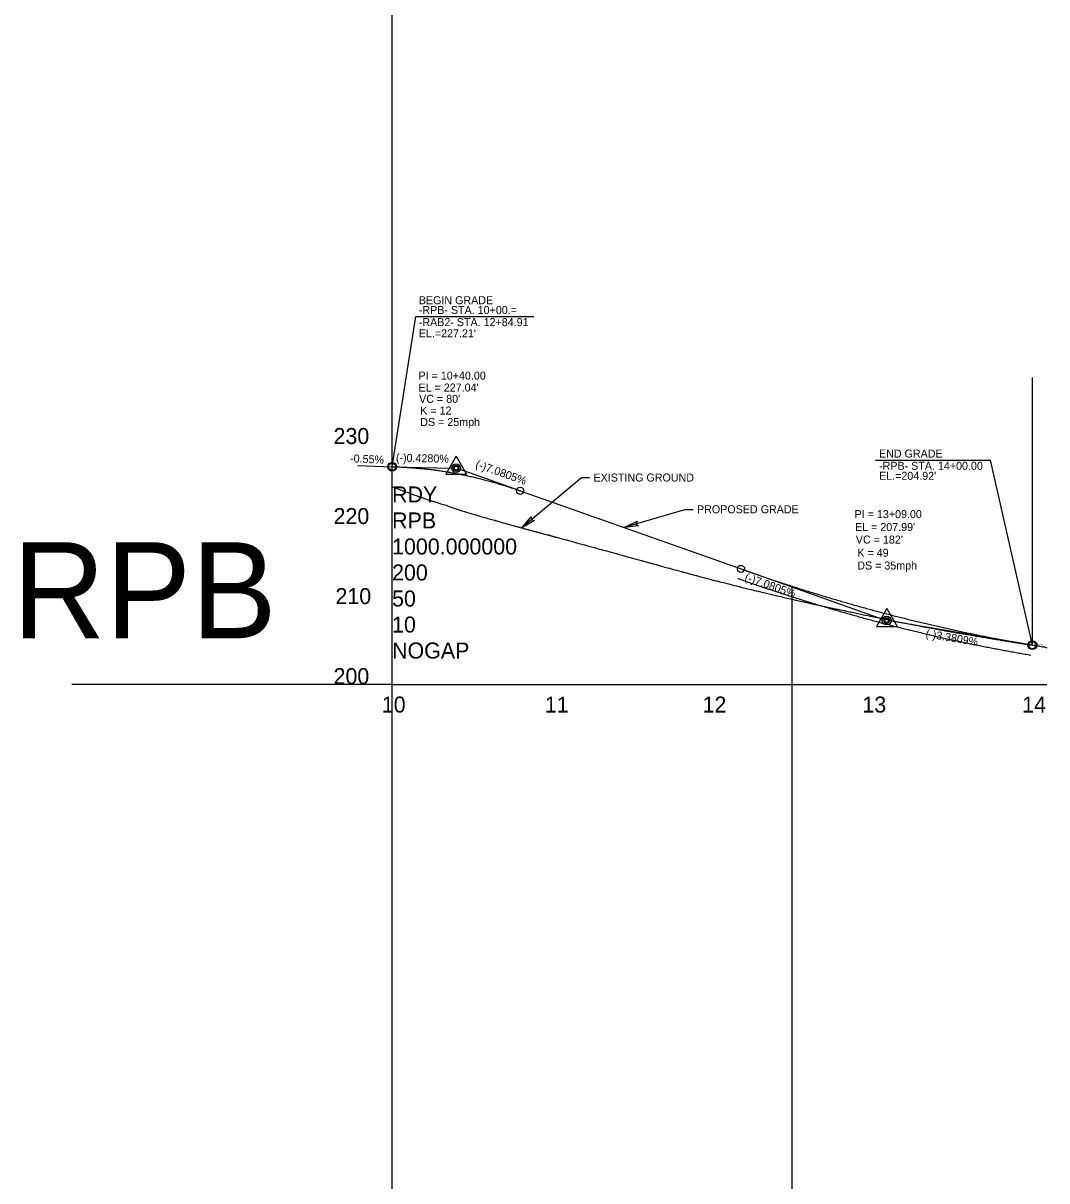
# Model space of a CAD drawing. Extents: x 2115752 to 2121174, y 562881 to 567245.
# Drawn here: x 2116466 to 2117105, y 564327 to 565050 of the extents above; entities that cross this region are included whole.
import ezdxf

# ---------------------------------------------------------------- set-up
doc = ezdxf.new("R2010")
doc.units = 0
for name, color, linetype in [('Exist Profile Cell', 7, 'Continuous'), ('Exist Vertical Profile Ground Line', 7, 'Continuous'), ('Exist Vertical Profile Horizontal Axis Label Major', 7, 'Continuous'), ('Exist Vertical Profile Vertical Axis Label', 7, 'Continuous'), ('Prop PFL VPI Symbol CELL', 7, 'Continuous'), ('Prop Terminator CELL', 7, 'Continuous'), ('Prop Vertical Profile Curve Label', 7, 'Continuous'), ('Prop Vertical Profile Grade', 7, 'Continuous'), ('Prop Vertical Profile Grade Label', 7, 'Continuous'), ('Prop VPI Label', 7, 'Continuous'), ('Scratch_Level_1', 7, 'Continuous')]:
    doc.layers.add(name, color=color, linetype=linetype)

msp = doc.modelspace()

# ---------------------------------------------------------------- linework, layer by layer
at = {"layer": 'Exist Profile Cell'}
for q in [(2116696.3, 564887.02), (2117105.35, 564637.02), (2116696.3, 564637.02)]:
    msp.add_line((2116696.3, 564637.02), q, dxfattribs=at)
at = {"layer": 'Exist Vertical Profile Ground Line'}
for points in [[(2116696.3, 564760.59), (2116696.8, 564760.39), (2116697.3, 564760.25), (2116699.53, 564759.41), (2116701.4, 564758.73), (2116702.12, 564758.46), (2116702.66, 564758.26), (2116703.96, 564757.68), (2116705.79, 564757.11), (2116707.51, 564756.4), (2116708.91, 564755.92), (2116709.33, 564755.73), (2116709.91, 564755.57), (2116712.03, 564754.81), (2116712.91, 564754.45), (2116714.1, 564754.12), (2116715.14, 564753.76), (2116716.48, 564753.23), (2116718.31, 564752.67), (2116720.06, 564752.04), (2116721.37, 564751.63), (2116721.85, 564751.46), (2116722.49, 564751.28), (2116724.45, 564750.65), (2116726.71, 564749.99), (2116727.54, 564749.74), (2116730.01, 564748.97), (2116730.88, 564748.68), (2116732.55, 564748.07), (2116733.77, 564747.65), (2116734.34, 564747.41), (2116735.1, 564747.16), (2116736.87, 564746.54), (2116739.32, 564745.73), (2116739.96, 564745.53), (2116741.47, 564745.04), (2116743.44, 564744.48), (2116745.04, 564743.98), (2116746.2, 564743.65), (2116747.7, 564743.21), (2116748.63, 564742.95), (2116749.31, 564742.75), (2116750.43, 564742.42), (2116752.42, 564741.87), (2116754.03, 564741.4), (2116755.82, 564740.9), (2116756.21, 564740.79), (2116757.61, 564740.41), (2116758.65, 564740.11), (2116760.4, 564739.6), (2116761.17, 564739.38), (2116761.76, 564739.2), (2116762.97, 564738.85), (2116764.87, 564738.32), (2116766.53, 564737.83), (2116768, 564737.44), (2116768.34, 564737.35), (2116768.8, 564737.22), (2116771.09, 564736.55), (2116771.87, 564736.33), (2116772.96, 564736.03), (2116774.2, 564735.68), (2116777.29, 564734.84), (2116779.02, 564734.38), (2116780.4, 564734), (2116781.24, 564733.77), (2116782.56, 564733.41), (2116783.52, 564733.15), (2116784.39, 564732.93), (2116785.56, 564732.62), (2116786.63, 564732.34), (2116789.74, 564731.54), (2116791.57, 564731.06), (2116792.87, 564730.72), (2116793.92, 564730.44), (2116795.94, 564729.9), (2116798.1, 564729.31), (2116798.66, 564729.16), (2116799.07, 564729.05), (2116800.5, 564728.65), (2116802.37, 564728.14), (2116805.3, 564727.35), (2116806.51, 564727), (2116808.36, 564726.49), (2116809.36, 564726.21), (2116810.71, 564725.84), (2116811.15, 564725.72), (2116811.47, 564725.63), (2116812.94, 564725.22), (2116814.92, 564724.68), (2116816.55, 564724.2), (2116817.75, 564723.87), (2116818.35, 564723.7), (2116819.15, 564723.48), (2116820.87, 564723), (2116823.34, 564722.34), (2116823.98, 564722.17), (2116825.77, 564721.69), (2116827.08, 564721.32), (2116827.54, 564721.2), (2116830.16, 564720.48)], [(2116830.16, 564720.48), (2116831.77, 564720.05), (2116833.25, 564719.64), (2116836.36, 564718.8), (2116837.99, 564718.33), (2116839.79, 564717.86), (2116840.11, 564717.77), (2116842.64, 564717.08), (2116843.35, 564716.88), (2116844.3, 564716.63), (2116845.73, 564716.24), (2116848.8, 564715.4), (2116850.51, 564714.92), (2116851.98, 564714.52), (2116852.29, 564714.43), (2116852.68, 564714.33), (2116855.06, 564713.66), (2116857.02, 564713.12), (2116857.66, 564712.94), (2116858.15, 564712.8), (2116859.44, 564712.43), (2116861.32, 564711.92), (2116861.86, 564711.77), (2116864.36, 564711.07), (2116865.43, 564710.78), (2116866.59, 564710.44), (2116867.49, 564710.22), (2116868.39, 564709.98), (2116869.58, 564709.66), (2116870.18, 564709.49), (2116870.63, 564709.37), (2116871.96, 564708.99), (2116874.02, 564708.44), (2116876.85, 564707.66), (2116877.31, 564707.53), (2116877.92, 564707.37), (2116879.94, 564706.81), (2116882.23, 564706.2), (2116882.69, 564706.07), (2116883.04, 564705.97), (2116885.19, 564705.41), (2116886.14, 564705.15), (2116886.5, 564705.05), (2116888.06, 564704.61), (2116889.28, 564704.31), (2116889.88, 564704.16), (2116890.7, 564703.94), (2116891.65, 564703.67), (2116892.38, 564703.49), (2116893.44, 564703.21), (2116894.92, 564702.84), (2116895.5, 564702.69), (2116897.01, 564702.27), (2116898.61, 564701.88), (2116899.13, 564701.75), (2116901.71, 564701.07), (2116903.28, 564700.67), (2116904.82, 564700.27), (2116907.34, 564699.63), (2116907.94, 564699.48), (2116909.98, 564698.96), (2116911.4, 564698.6), (2116913.01, 564698.17), (2116914.16, 564697.9), (2116914.83, 564697.73), (2116915.77, 564697.5), (2116916.66, 564697.28), (2116917.28, 564697.12), (2116918.48, 564696.81), (2116920.4, 564696.36), (2116921.17, 564696.17), (2116923.48, 564695.61), (2116924.09, 564695.46), (2116926.61, 564694.85), (2116927.33, 564694.68), (2116928.37, 564694.43), (2116929.17, 564694.24), (2116929.72, 564694.11), (2116931.01, 564693.8), (2116932.85, 564693.38), (2116933.39, 564693.26), (2116935.93, 564692.66), (2116936.23, 564692.59), (2116936.66, 564692.49), (2116938.08, 564692.16), (2116939.05, 564691.94), (2116939.92, 564691.73), (2116941.12, 564691.47), (2116942.17, 564691.23), (2116945.27, 564690.53), (2116947.04, 564690.12), (2116948.4, 564689.82), (2116948.9, 564689.7), (2116949.51, 564689.57), (2116951.48, 564689.13), (2116952.32, 564688.93), (2116953.56, 564688.66), (2116954.18, 564688.52), (2116954.61, 564688.43), (2116957.74, 564687.72), (2116959.48, 564687.31)], [(2116959.48, 564687.31), (2116960.82, 564687.01), (2116961.35, 564686.89), (2116962.11, 564686.73), (2116963.93, 564686.33), (2116966.09, 564685.86), (2116966.65, 564685.75), (2116967.04, 564685.66), (2116968.52, 564685.32), (2116970.49, 564684.92), (2116973.24, 564684.33), (2116973.83, 564684.19), (2116974.69, 564684.02), (2116976.35, 564683.66), (2116978.7, 564683.17), (2116979.16, 564683.08), (2116979.49, 564683.01), (2116981.04, 564682.67), (2116982.59, 564682.37), (2116983, 564682.29), (2116984.49, 564681.97), (2116985.69, 564681.72), (2116986.38, 564681.57), (2116987.34, 564681.38), (2116988.86, 564681.07), (2116991.92, 564680.43), (2116993.42, 564680.13), (2116995.01, 564679.8), (2116995.5, 564679.7), (2116997.1, 564679.38), (2116998.16, 564679.17), (2116999.78, 564678.84), (2117000.57, 564678.68), (2117001.21, 564678.55), (2117002.46, 564678.28), (2117004.42, 564677.9), (2117005.18, 564677.75), (2117007.46, 564677.27), (2117007.84, 564677.19), (2117008.36, 564677.09), (2117010.62, 564676.65), (2117012.5, 564676.29), (2117013.69, 564676.05), (2117016.8, 564675.44), (2117017.35, 564675.33), (2117019.91, 564674.82), (2117020.75, 564674.65), (2117022.98, 564674.2), (2117024.95, 564673.82), (2117025.65, 564673.69), (2117026.15, 564673.59), (2117027.5, 564673.29), (2117029.4, 564672.96), (2117032.3, 564672.4), (2117033.34, 564672.2), (2117034.58, 564671.95), (2117035.5, 564671.79), (2117036.46, 564671.6), (2117037.6, 564671.41), (2117038.54, 564671.24), (2117041.18, 564670.77), (2117041.77, 564670.67), (2117043.53, 564670.34), (2117044.84, 564670.12), (2117045.39, 564670.02), (2117046.05, 564669.92), (2117047.91, 564669.6), (2117048.96, 564669.41), (2117050.21, 564669.21), (2117050.62, 564669.14), (2117050.96, 564669.08), (2117053.13, 564668.72), (2117054.39, 564668.51), (2117057.22, 564668.02), (2117057.83, 564667.91), (2117058.59, 564667.79), (2117059.59, 564667.62), (2117060.34, 564667.49), (2117061.44, 564667.29), (2117062.78, 564667.08), (2117063.42, 564666.97), (2117065.02, 564666.68), (2117066.98, 564666.36), (2117068.59, 564666.07), (2117069.64, 564665.9), (2117070.31, 564665.78), (2117071.23, 564665.64), (2117072.15, 564665.48), (2117072.77, 564665.37), (2117073.91, 564665.17), (2117075.9, 564664.85), (2117077.51, 564664.57), (2117079.02, 564664.34), (2117079.74, 564664.23), (2117081.1, 564663.99), (2117082.17, 564663.82), (2117083.92, 564663.54), (2117084.67, 564663.42), (2117085.28, 564663.32), (2117088.34, 564662.83), (2117089.04, 564662.73)], [(2117089.04, 564662.73), (2117091.39, 564662.36), (2117091.76, 564662.31), (2117092.22, 564662.24), (2117094.52, 564661.88), (2117095.34, 564661.75), (2117096.44, 564661.59), (2117097.16, 564661.48), (2117097.66, 564661.4), (2117098.94, 564661.2), (2117100.78, 564660.96), (2117102.54, 564660.68), (2117103.95, 564660.48), (2117104.36, 564660.42), (2117105.35, 564659.88)]]:
    msp.add_lwpolyline(points, dxfattribs=at)
at = {"layer": 'Prop PFL VPI Symbol CELL'}
for p, q in [((2116736.3, 564779.71), (2116729.85, 564768.51)), ((2116736.3, 564779.71), (2116742.8, 564768.51)), ((2116729.85, 564768.51), (2116742.8, 564768.51)), ((2117005.3, 564684.47), (2116998.85, 564673.27)), ((2117005.3, 564684.47), (2117011.8, 564673.27)), ((2116998.85, 564673.27), (2117011.8, 564673.27))]:
    msp.add_line(p, q, dxfattribs=at)
for centre, radius in [((2116736.3, 564772.22), 1.75), ((2116736.3, 564772.22), 1.2), ((2117005.3, 564676.99), 1.75), ((2117005.3, 564676.99), 1.2)]:
    msp.add_circle(centre, radius, dxfattribs=at)
at = {"layer": 'Prop Terminator CELL'}
for points in [[(2116785.19, 564739.42), (2116777.29, 564734.84), (2116783.21, 564741.87), (2116783.35, 564739.9)], [(2116850.35, 564736.1), (2116841.27, 564735.06), (2116849.51, 564739.14), (2116848.85, 564737.28)]]:
    msp.add_lwpolyline(points, close=True, dxfattribs=at)
at = {"layer": 'Prop Vertical Profile Curve Label'}
for centre in [(2116696.3, 564773.08), (2116776.3, 564758.06), (2116914.3, 564709.21), (2117096.3, 564661.61)]:
    msp.add_circle(centre, 2.25, dxfattribs=at)
at = {"layer": 'Prop Vertical Profile Grade'}
for p, q in [((2116776.3, 564758.06), (2116914.3, 564709.21)), ((2117095.3, 564661.78), (2117096.3, 564661.61))]:
    msp.add_line(p, q, dxfattribs=at)
for points in [[(2116696.3, 564773.08), (2116697.9, 564773.04), (2116699.5, 564772.99), (2116701.1, 564772.93), (2116702.7, 564772.86), (2116704.3, 564772.78), (2116705.9, 564772.68), (2116707.5, 564772.58), (2116709.1, 564772.47), (2116710.7, 564772.34), (2116712.3, 564772.21), (2116713.9, 564772.06), (2116715.5, 564771.9), (2116717.1, 564771.74), (2116718.7, 564771.56), (2116720.3, 564771.37), (2116721.9, 564771.17), (2116723.5, 564770.96), (2116725.1, 564770.74), (2116726.7, 564770.51), (2116728.3, 564770.27), (2116729.9, 564770.01), (2116731.5, 564769.75), (2116733.1, 564769.48), (2116734.7, 564769.19), (2116736.3, 564768.9), (2116737.9, 564768.59), (2116739.5, 564768.28), (2116741.1, 564767.95), (2116742.7, 564767.61), (2116744.3, 564767.26), (2116745.9, 564766.9), (2116747.5, 564766.54), (2116749.1, 564766.15), (2116750.7, 564765.76), (2116752.3, 564765.36), (2116753.9, 564764.95), (2116755.5, 564764.53), (2116757.1, 564764.09), (2116758.7, 564763.65), (2116760.3, 564763.2), (2116761.9, 564762.73), (2116763.5, 564762.25), (2116765.1, 564761.77), (2116766.7, 564761.27), (2116768.3, 564760.76), (2116769.9, 564760.24), (2116771.5, 564759.71), (2116773.1, 564759.18), (2116774.7, 564758.62), (2116776.3, 564758.06)], [(2116914.3, 564709.21), (2116917.94, 564707.93), (2116921.58, 564706.66), (2116925.22, 564705.4), (2116928.86, 564704.16), (2116932.5, 564702.93), (2116936.14, 564701.72), (2116939.78, 564700.52), (2116943.42, 564699.33), (2116947.06, 564698.16), (2116950.7, 564696.99), (2116954.34, 564695.85), (2116957.98, 564694.71), (2116961.62, 564693.59), (2116965.26, 564692.49), (2116968.9, 564691.39), (2116972.54, 564690.31), (2116976.18, 564689.25), (2116979.82, 564688.19), (2116983.46, 564687.15), (2116987.1, 564686.13), (2116990.74, 564685.12), (2116994.38, 564684.12), (2116998.02, 564683.13), (2117001.66, 564682.16), (2117005.3, 564681.2), (2117008.94, 564680.25), (2117012.58, 564679.32), (2117016.22, 564678.4), (2117019.86, 564677.5), (2117023.5, 564676.61), (2117027.14, 564675.73), (2117030.78, 564674.87), (2117034.42, 564674.01), (2117038.06, 564673.18), (2117041.7, 564672.35), (2117045.34, 564671.54), (2117048.98, 564670.75), (2117052.62, 564669.96), (2117056.26, 564669.19), (2117059.9, 564668.43), (2117063.54, 564667.69), (2117067.18, 564666.96), (2117070.82, 564666.25), (2117074.46, 564665.54), (2117078.1, 564664.85), (2117081.74, 564664.18), (2117085.38, 564663.51), (2117089.02, 564662.87), (2117092.66, 564662.23), (2117096.3, 564661.61)]]:
    msp.add_spline(points, degree=3, dxfattribs=at)
at = {"layer": 'Prop VPI Label'}
for p, q in [((2116696.3, 564773.08), (2116711.22, 564866.89)), ((2116711.22, 564866.89), (2116784.91, 564866.89)), ((2116674.78, 564773.95), (2116696.3, 564773.08)), ((2116696.3, 564773.08), (2116733.55, 564772.28)), ((2116776.3, 564758.06), (2116738.9, 564771.31)), ((2116998.27, 564777.09), (2117070.2, 564777.09)), ((2117096.3, 564661.61), (2117070.2, 564777.09)), ((2116914.3, 564709.21), (2117002.71, 564677.91)), ((2117096.3, 564661.61), (2117008.02, 564676.53))]:
    msp.add_line(p, q, dxfattribs=at)
for points in [[(2116819.71, 564766.07), (2116814.74, 564766.07), (2116777.29, 564734.84)], [(2116884.38, 564746.12), (2116879.08, 564746.12), (2116841.27, 564735.06)]]:
    msp.add_lwpolyline(points, dxfattribs=at)
for centre in [(2116696.3, 564773.08), (2116736.3, 564772.22), (2117005.3, 564676.99), (2117096.3, 564661.61)]:
    msp.add_circle(centre, 2.75, dxfattribs=at)
at = {"layer": 'Scratch_Level_1'}
for p, q in [((2116696.3, 564637.02), (2116696.3, 565506.42)), ((2117096.3, 564661.61), (2117096.3, 564828.74)), ((2116718.31, 564752.67), (2116724.45, 564750.65)), ((2116768, 564737.44), (2116798.66, 564729.16)), ((2116946.3, 563767.63), (2116946.3, 564698.4)), ((2117046.3, 564669.87), (2117066.98, 564666.36)), ((2117076.3, 564664.78), (2117088.34, 564662.83)), ((2117096.3, 564661.61), (2117100.78, 564660.96)), ((2116696.3, 564637.02), (2116496.27, 564637.02)), ((2116696.3, 563767.63), (2116696.3, 564637.02))]:
    msp.add_line(p, q, dxfattribs=at)
msp.add_spline([(2116912.23, 564703.31), (2116915.88, 564702.03), (2116919.54, 564700.75), (2116923.2, 564699.49), (2116926.86, 564698.24), (2116930.52, 564697.01), (2116934.18, 564695.79), (2116937.84, 564694.58), (2116941.5, 564693.38), (2116945.16, 564692.2), (2116948.82, 564691.04), (2116952.48, 564689.88), (2116956.14, 564688.74), (2116959.8, 564687.62), (2116963.46, 564686.5), (2116967.12, 564685.4), (2116970.78, 564684.32), (2116974.44, 564683.25), (2116978.1, 564682.19), (2116981.76, 564681.14), (2116985.42, 564680.11), (2116989.08, 564679.09), (2116992.74, 564678.09), (2116996.4, 564677.1), (2117000.06, 564676.12), (2117003.72, 564675.15), (2117007.38, 564674.2), (2117011.04, 564673.27), (2117014.71, 564672.34), (2117018.37, 564671.43), (2117022.03, 564670.54), (2117025.69, 564669.65), (2117029.35, 564668.78), (2117033.01, 564667.93), (2117036.67, 564667.08), (2117040.33, 564666.26), (2117044, 564665.44), (2117047.66, 564664.64), (2117051.32, 564663.85), (2117054.98, 564663.07), (2117058.64, 564662.31), (2117062.3, 564661.57), (2117065.97, 564660.83), (2117069.63, 564660.11), (2117073.29, 564659.4), (2117076.95, 564658.71), (2117080.61, 564658.03), (2117084.28, 564657.36), (2117087.94, 564656.71), (2117091.6, 564656.07), (2117095.25, 564655.45)], degree=3, dxfattribs=at)

# ---------------------------------------------------------------- texts
at = {"layer": 'Exist Profile Cell'}
for s, p in [('RDY', (2116696.3, 564750.77)), ('RPB', (2116696.3, 564734.52)), ('1000.000000', (2116696.3, 564718.27)), ('200', (2116696.3, 564702.02)), ('50', (2116696.3, 564685.77)), ('10', (2116696.3, 564669.52)), ('NOGAP', (2116696.3, 564653.27))]:
    msp.add_text(s, height=10, dxfattribs=at).set_placement(p)
at = {"layer": 'Exist Vertical Profile Horizontal Axis Label Major'}
for s, p in [('10', (2116689.89, 564619.52)), ('11', (2116791.73, 564619.52)), ('12', (2116890.28, 564619.52)), ('13', (2116990.11, 564619.52)), ('14', (2117089.95, 564619.52))]:
    msp.add_text(s, height=10, dxfattribs=at).set_placement(p)
at = {"layer": 'Exist Vertical Profile Vertical Axis Label'}
for s, height, p in [('230', 10, (2116659.74, 564787.27)), ('220', 10, (2116659.74, 564737.27)), ('RPB', 60, (2116459.24, 564665.92)), ('210', 10, (2116660.93, 564687.27)), ('200', 10, (2116659.74, 564637.27))]:
    msp.add_text(s, height=height, dxfattribs=at).set_placement(p)
at = {"layer": 'Prop Vertical Profile Curve Label'}
for s, p in [("VC = 80'", (2116713.19, 564813)), ('K = 12', (2116713.91, 564805.68)), ('DS = 25mph', (2116713.9, 564798.53)), ("VC = 182'", (2116986.03, 564725.08)), ('K = 49', (2116986.97, 564716.83)), ('DS = 35mph', (2116986.94, 564708.88))]:
    msp.add_text(s, height=5, dxfattribs=at).set_placement(p)
at = {"layer": 'Prop Vertical Profile Grade Label'}
for s, rotation, p in [('-0.55%', 357.19214, (2116669.97, 564775.91)), ('(-)0.4280%', 358.77406, (2116698.64, 564776.26)), ('(-)7.0805%', 340.50474, (2116747.99, 564772.68)), ('(-)7.0805%', 340.50474, (2116916.16, 564702.13)), ('(-)3.3809%', 350.40503, (2117029.34, 564666.56))]:
    msp.add_text(s, height=5, rotation=rotation, dxfattribs=at).set_placement(p)
at = {"layer": 'Prop VPI Label'}
for s, p in [('BEGIN GRADE', (2116712.99, 564874.59)), ('-RPB- STA. 10+00.=', (2116712.99, 564868.49)), ('-RAB2- STA. 12+84.91', (2116712.99, 564860.91)), ("EL.=227.21'", (2116712.99, 564853.91)), ('PI = 10+40.00', (2116712.81, 564827.5)), ("EL = 227.04'", (2116712.81, 564820.06)), ('END GRADE', (2117000.5, 564778.79)), ('-RPB- STA. 14+00.00', (2117000.53, 564771.15)), ('EXISTING GROUND', (2116822.15, 564763.83)), ("EL.=204.92'", (2117000.53, 564764.9)), ('PROPOSED GRADE', (2116886.8, 564744.02)), ('PI = 13+09.00', (2116985.26, 564740.99)), ("EL = 207.99'", (2116985.52, 564732.91))]:
    msp.add_text(s, height=5, dxfattribs=at).set_placement(p)
at = {"layer": 'Scratch_Level_1'}
msp.add_text('-2.8880 %', height=1, rotation=351.78316, dxfattribs=at).set_placement((2117096.76, 564661.87))

doc.saveas('drawing.dxf')
